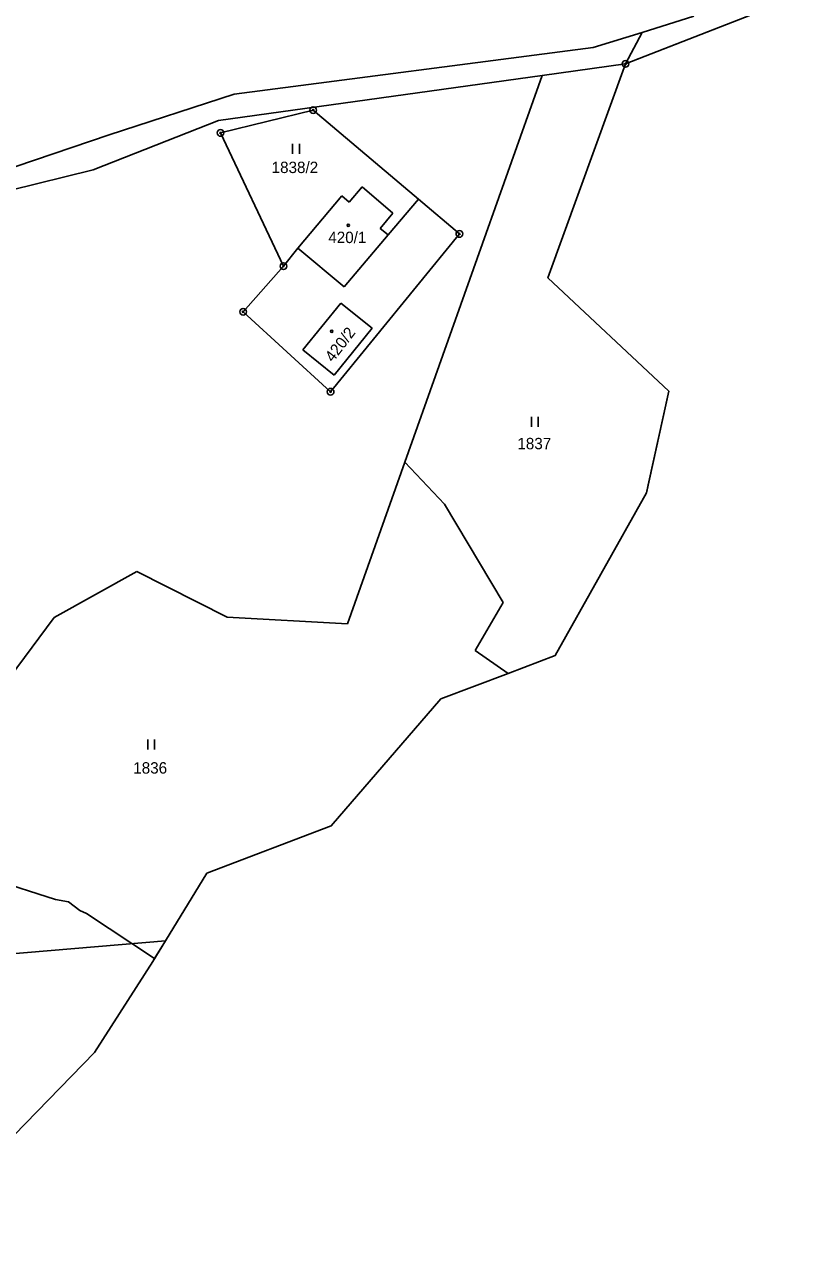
# Model space of a CAD drawing. Extents: x -445050 to -440454, y -1134563 to -1129741.
# Drawn here: x -443437.5 to -443320.6, y -1133750.2 to -1133568.6 of the extents above; entities that cross this region are included whole.
import ezdxf

# ---------------------------------------------------------------- set-up
doc = ezdxf.new("R2010")
doc.units = 0
for name, color, linetype in [('Vrstva 1', 7, 'Continuous'), ('Vrstva 13', 7, 'Continuous'), ('Vrstva 18', 7, 'Continuous'), ('Vrstva 19', 7, 'Continuous'), ('Vrstva 24', 7, 'Continuous'), ('Vrstva 25', 7, 'Continuous'), ('Vrstva 3', 7, 'Continuous'), ('Vrstva 37', 7, 'Continuous'), ('Vrstva 4', 7, 'Continuous'), ('Vrstva 52', 7, 'Continuous')]:
    doc.layers.add(name, color=color, linetype=linetype)

msp = doc.modelspace()

# ---------------------------------------------------------------- linework, layer by layer
at = {"layer": 'Vrstva 1'}
for points in [[(-443345.3, -1133569.83), (-443337.57, -1133567.4)], [(-443352.62, -1133572.09), (-443345.3, -1133569.83)], [(-443347.77, -1133574.52), (-443345.3, -1133569.83)], [(-443406.2, -1133579.03), (-443352.62, -1133572.09)], [(-443360.21, -1133576.25), (-443347.77, -1133574.52)], [(-443408.53, -1133582.99), (-443360.21, -1133576.25)], [(-443360.21, -1133576.25), (-443380.72, -1133633.98)], [(-443424.87, -1133585.13), (-443406.2, -1133579.03)], [(-443394.42, -1133581.42), (-443408.25, -1133584.83)], [(-443394.42, -1133581.42), (-443378.7, -1133594.73)], [(-443427.25, -1133590.33), (-443408.53, -1133582.99)], [(-443441.64, -1133590.79), (-443424.87, -1133585.13)], [(-443408.25, -1133584.83), (-443398.85, -1133604.72)], [(-443439.76, -1133593.44), (-443427.25, -1133590.33)], [(-443387.1, -1133592.87), (-443389.05, -1133595.18)], [(-443387.1, -1133592.87), (-443382.51, -1133596.8)], [(-443390.12, -1133594.23), (-443396.69, -1133602.03)], [(-443390.12, -1133594.23), (-443389.05, -1133595.18)], [(-443383.24, -1133600.06), (-443378.7, -1133594.73)], [(-443378.7, -1133594.73), (-443372.58, -1133599.91)], [(-443384.39, -1133599.09), (-443382.51, -1133596.8)], [(-443384.39, -1133599.09), (-443383.24, -1133600.06)], [(-443372.58, -1133599.91), (-443391.81, -1133623.46)], [(-443396.69, -1133602.03), (-443398.85, -1133604.72)], [(-443398.85, -1133604.72), (-443404.88, -1133611.53)], [(-443390.27, -1133610.22), (-443395.94, -1133617.22)], [(-443385.63, -1133613.97), (-443390.27, -1133610.22)], [(-443391.81, -1133623.46), (-443404.88, -1133611.53)], [(-443391.28, -1133620.97), (-443385.63, -1133613.97)], [(-443395.94, -1133617.22), (-443391.28, -1133620.97)], [(-443380.72, -1133633.98), (-443389.29, -1133658.11)], [(-443380.72, -1133633.98), (-443374.82, -1133640.27)], [(-443374.82, -1133640.27), (-443366.06, -1133654.95)], [(-443420.74, -1133650.29), (-443433.09, -1133657.16)], [(-443407.25, -1133657.1), (-443420.74, -1133650.29)], [(-443366.06, -1133654.95), (-443370.23, -1133662.09)], [(-443433.09, -1133657.16), (-443448.72, -1133678.18)], [(-443389.29, -1133658.11), (-443407.25, -1133657.1)], [(-443370.23, -1133662.09), (-443365.32, -1133665.52)], [(-443486.61, -1133711.38), (-443416.48, -1133705.44)]]:
    msp.add_lwpolyline(points, dxfattribs=at)
at = {"layer": 'Vrstva 13'}
for points in [[(-443347.77, -1133574.52), (-443320.58, -1133563.84)], [(-443359.36, -1133606.47), (-443347.77, -1133574.52)], [(-443359.36, -1133606.47), (-443341.31, -1133623.39)], [(-443341.31, -1133623.39), (-443344.65, -1133638.54)], [(-443358.28, -1133662.84), (-443344.65, -1133638.54)], [(-443358.28, -1133662.84), (-443365.32, -1133665.52)], [(-443365.32, -1133665.52), (-443375.33, -1133669.32)], [(-443391.72, -1133688.25), (-443375.33, -1133669.32)], [(-443410.29, -1133695.35), (-443391.72, -1133688.25)], [(-443410.29, -1133695.35), (-443416.48, -1133705.44)], [(-443416.48, -1133705.44), (-443418.37, -1133708.52)], [(-443427.09, -1133722.11), (-443418.37, -1133708.52)], [(-443449.43, -1133745.05), (-443427.09, -1133722.11)]]:
    msp.add_lwpolyline(points, dxfattribs=at)
at = {"layer": 'Vrstva 24'}
for centre, radius in [((-443347.77, -1133574.52), 0.5), ((-443347.77, -1133574.52), 0.1), ((-443394.42, -1133581.42), 0.5), ((-443394.42, -1133581.42), 0.1), ((-443408.25, -1133584.83), 0.5), ((-443408.25, -1133584.83), 0.1), ((-443372.58, -1133599.91), 0.5), ((-443372.58, -1133599.91), 0.1), ((-443398.85, -1133604.72), 0.5), ((-443398.85, -1133604.72), 0.1), ((-443404.88, -1133611.53), 0.5), ((-443404.88, -1133611.53), 0.1), ((-443391.81, -1133623.46), 0.5), ((-443391.81, -1133623.46), 0.1)]:
    msp.add_circle(centre, radius, dxfattribs=at)
at = {"layer": 'Vrstva 25'}
for p, q in [((-443397.48, -1133587.96), (-443397.48, -1133586.46)), ((-443396.48, -1133587.96), (-443396.48, -1133586.46)), ((-443361.82, -1133628.69), (-443361.82, -1133627.19)), ((-443360.82, -1133628.69), (-443360.82, -1133627.19)), ((-443419.11, -1133676.87), (-443419.11, -1133675.37)), ((-443418.11, -1133676.87), (-443418.11, -1133675.37))]:
    msp.add_line(p, q, dxfattribs=at)
for centre in [(-443389.18, -1133598.6), (-443391.64, -1133614.44)]:
    msp.add_circle(centre, 0.175, dxfattribs=at)
at = {"layer": 'Vrstva 3'}
for points in [[(-443387.1, -1133592.87), (-443389.05, -1133595.18)], [(-443387.1, -1133592.87), (-443382.51, -1133596.8)], [(-443390.12, -1133594.23), (-443396.69, -1133602.03)], [(-443390.12, -1133594.23), (-443389.05, -1133595.18)], [(-443384.39, -1133599.09), (-443382.51, -1133596.8)], [(-443384.39, -1133599.09), (-443383.24, -1133600.06)], [(-443389.8, -1133607.78), (-443383.24, -1133600.06)], [(-443389.8, -1133607.78), (-443396.69, -1133602.03)], [(-443390.27, -1133610.22), (-443395.94, -1133617.22)], [(-443385.63, -1133613.97), (-443390.27, -1133610.22)], [(-443391.28, -1133620.97), (-443385.63, -1133613.97)], [(-443395.94, -1133617.22), (-443391.28, -1133620.97)]]:
    msp.add_lwpolyline(points, dxfattribs=at)
at = {"layer": 'Vrstva 37'}
for centre in [(-443389.18, -1133598.6), (-443391.64, -1133614.44)]:
    msp.add_circle(centre, 0.175, dxfattribs=at)
at = {"layer": 'Vrstva 4'}
for points in [[(-443389.8, -1133607.78), (-443383.24, -1133600.06)], [(-443389.8, -1133607.78), (-443396.69, -1133602.03)]]:
    msp.add_lwpolyline(points, dxfattribs=at)
at = {"layer": 'Vrstva 52'}
for points in [[(-443320.58, -1133563.84), (-443345.72, -1133573.72), (-443347.77, -1133574.52), (-443359.36, -1133606.47), (-443341.31, -1133623.39), (-443344.39, -1133637.34), (-443344.65, -1133638.54), (-443358.28, -1133662.84), (-443365.32, -1133665.52), (-443375.33, -1133669.32), (-443391.72, -1133688.25), (-443410.29, -1133695.35), (-443416.48, -1133705.44), (-443418.1, -1133708.08)], [(-443418.1, -1133708.08), (-443428.25, -1133701.34), (-443429.28, -1133700.89), (-443430.93, -1133699.6), (-443432.91, -1133699.28), (-443442.27, -1133696.3)], [(-443418.1, -1133708.08), (-443418.37, -1133708.52), (-443427.09, -1133722.11), (-443449.43, -1133745.05), (-443466.21, -1133748.87), (-443468.58, -1133753.29), (-443480.24, -1133774.99), (-443494.1, -1133788.49), (-443508.55, -1133799.78), (-443519.86, -1133810.93), (-443525.44, -1133816.12), (-443568.24, -1133868.28), (-443571.4, -1133872.62), (-443601.28, -1133913.69), (-443619.02, -1133939.8), (-443631.11, -1133957.59)]]:
    msp.add_lwpolyline(points, dxfattribs=at)

# ---------------------------------------------------------------- texts
at = {"layer": 'Vrstva 18'}
for s, p in [('1838/2', (-443400.62, -1133590.82)), ('1837', (-443363.93, -1133632.05)), ('1836', (-443421.28, -1133680.47))]:
    msp.add_text(s, height=1.7, dxfattribs=at).set_placement(p)
at = {"layer": 'Vrstva 19'}
msp.add_text('420/1', height=1.7, dxfattribs=at).set_placement((-443392.16, -1133601.27))
msp.add_text('420/2', height=1.7, rotation=52.4313, dxfattribs=at).set_placement((-443391.47, -1133619.16))

doc.saveas('drawing.dxf')
